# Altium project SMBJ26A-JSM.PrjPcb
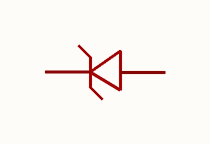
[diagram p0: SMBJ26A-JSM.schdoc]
1 sheet, 1 parts. Net scope: global (net labels, ports and power ports of the same name join across sheets).

## Sheet SMBJ26A-JSM.schdoc
size 127 x 101 mm

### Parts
D?  smbj26a-jsm  [SMB_L4.6-W3.6-LS5.3-RD]  (value not drawn)

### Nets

Not connected (* = marked no-connect by the designer): D? 1(C) 2(A)

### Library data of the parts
D? = smbj26a-jsm: 极性:单向;反向截止电压(Vrwm):26V;钳位电压:42.1V;峰值脉冲电流(Ipp):14.3A;峰值脉冲功率(Ppp):600W;击穿电压(VBR):31.9V;; Manufacturer: JSMSEMI(杰盛微); AddInBom: yes; ModelId: 5e8926c661484ff2a35b83e5ae62aeb9; ModelTransform: 212.598,141.732,0,0,0,0,0,0,0; Polarity: 单向; Reverse Stand-Off Voltage (Vrwm): 26V; Clamping Voltage: 42.1V; Peak Pulse Current (Ipp): 14.3A; Peak Pulse Power Dissipation (Ppp): 600W; Voltage - Breakdown: 31.9V; Reverse Leakage Current (Ir): 1uA; Number of Channels: 单路; Type: TVS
